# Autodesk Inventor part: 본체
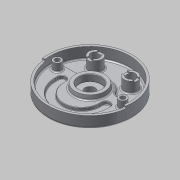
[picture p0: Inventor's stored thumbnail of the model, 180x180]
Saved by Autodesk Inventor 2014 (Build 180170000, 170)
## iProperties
Created: 2015-06
Part Number: 본체
Material: 알루미늄 6061
Document SubType Name: Modeling
Designer: MYHOME
Mass: 1071 g
Surface Area: 1034.49 cm^2
Volume: 395.202 cm^3
Density: 2.71 g/cm^3
Appearance: 알루미늄 - 평지
Author: MYHOME
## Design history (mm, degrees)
sketch "스케치1"
  geometry: C1 r 95 at (0, 0); 1 further point
  constraints: 1 centre point, 1 coincident
  dimensions: "d0" = 190 diameter of C1
extrude "돌출1" new body sketch "스케치1" distance "d1" = 32; taper "d2" = 0 deg
sketch "스케치2"
  geometry: C1 r 95 at (0, 0) reference; C2 r 90 at (0, 0)
  constraints: 1 centre point, 1 coincident
  dimensions: "d3" = 180 diameter of C2
extrude "돌출2" cut sketch "스케치2" distance "d4" = 18; taper "d5" = 0 deg
sketch "스케치3"
  geometry: L1 (-88.566, 16)-(-38.833, 16); L2 (-38.833, 16)-(38.833, 16); L3 (38.833, 16)-(88.566, 16); A1 r 90 centre (0, 0) between (88.566, 16) and (-88.566, 16) reference; A2 r 42 centre (0, 0) between (-38.833, 16) and (38.833, 16)
  constraints: 6 end point, 4 point on circle, 3 horizontal, 1 centre point, 1 coincident
  dimensions: "d6" = 84 diameter of A2; "d7" = 16 distance from line of A2.centre L1
extrude "돌출3" cut sketch "스케치3" distance "d8" = 7; taper "d9" = 0 deg
fillet "모깎기1" dims "d10" = 10
sketch "스케치4"
  geometry: L1 (75.657, 16)-(45.033, 16) reference; L2 (-50, -19)-(-50, -14); L3 (-59, -19)-(-59, -14); L4 (-41, -14)-(-41, -19); L5 (50, -19)-(50, -14); L6 (41, -19)-(41, -14); L7 (59, -14)-(59, -19); A1 r 90 centre (0, 0) between (-85.114, 29.25) and (85.114, 29.25) reference; A2 r 50 centre (0, -19) between (-50, -19) and (50, -19); A3 r 59 centre (0, -19) between (-59, -19) and (59, -19); A4 r 41 centre (0, -19) between (-41, -19) and (41, -19); A5 r 9 centre (-50, -19) between (-41, -19) and (-59, -19); A6 r 9 centre (50, -19) between (59, -19) and (41, -19); A7 r 9 centre (-50, -19) between (-59, -19) and (-41, -19); A8 r 9 centre (-50, -14) between (-41, -14) and (-59, -14); A9 r 9 centre (50, -19) between (41, -19) and (59, -19); A10 r 9 centre (50, -14) between (59, -14) and (41, -14); 2 further points
  constraints: 18 point on circle, 16 end point, 14 tangent, 9 centre point, 3 parallel, 2 horizontal alignment, 2 midpoint, 1 perpendicular, 1 vertical alignment
  dimensions: "d11" = 59 radius of A3; "d12" = 18 distance of A3.end A4.end; "d13" = 19 distance of A1.centre A2.centre; "d19" = 5 distance of L2.end L2.start; "d20" = 18 distance of L3.end L4.start; "d21" = 5 distance of L5.start L5.end; "d22" = 18 distance of L7.end L6.start
extrude "돌출4" cut sketch "스케치4" distance "d23" = 7; taper "d24" = 0 deg
sketch "스케치5"
  geometry: C1 r 15 at (-40, 52); C2 r 15 at (40, 52); A1 r 90 centre (0, 0) between (85.114, 29.25) and (-85.114, 29.25) reference
  constraints: 2 centre point, 1 horizontal alignment
  dimensions: "d25" = 30 diameter of C1; "d26" = 30 diameter of C2; "d27" = 52 vertical distance of C1.centre A1.centre; "d28" = 40 horizontal distance of A1.centre C1.centre; "d29" = 40 horizontal distance of C2.centre A1.centre
extrude "돌출5" join sketch "스케치5" stored distance "d30" = 7; taper "d31" = 0 deg
sketch "스케치6"
  geometry: C1 r 15 at (0, 0) reference; C2 r 15 at (80, 0) reference; C3 r 10 at (0, 0); C4 r 10 at (80, 0); 1 further point
  constraints: 2 centre point, 2 coincident
  dimensions: "d32" = 20 diameter of C3; "d33" = 20 diameter of C4
extrude "돌출6" cut sketch "스케치6" stored distance "d34" = 7; taper "d35" = 0 deg
sketch "스케치7"
  geometry: L1 (65, 6)-(95, 6); L2 (95, 6)-(95, -6); L3 (95, -6)-(65, -6); L4 (65, -6)-(65, 6); L5 (6, -15)-(-6, -15); L6 (-6, -15)-(-6, 15); L7 (-6, 15)-(6, 15); L8 (6, 15)-(6, -15); C1 r 10 at (0, 0) reference; C2 r 15 at (0, 0) reference; C3 r 10 at (80, 0) reference; C4 r 15 at (80, 0) reference; 3 further points
  constraints: 16 end point, 4 parallel, 4 tangent, 2 horizontal, 2 midpoint, 2 perpendicular, 1 horizontal alignment, 1 vertical alignment
  dimensions: "d36" = 12 distance of L6.end L7.end; "d37" = 12 distance of L3.end L1.start
extrude "돌출7" cut sketch "스케치7" distance "d38" = 3; taper "d39" = 0 deg
sketch "스케치8"
  geometry: C1 r 9 at (-74, 0); C2 r 9 at (74, 0); A1 r 90 centre (0, 0) between (-85.114, 29.25) and (85.114, 29.25) reference
  constraints: 2 centre point, 2 horizontal alignment
  dimensions: "d40" = 18 diameter of C1; "d41" = 18 diameter of C2; "d42" = 74 distance of A1.centre C1.centre; "d43" = 74 distance of C2.centre A1.centre
extrude "돌출8" join sketch "스케치8" stored distance "d44" = 3; taper "d45" = 0 deg
sketch "스케치9"
  geometry: C1 r 9 at (0, 0) reference; C2 r 9 at (148, 0) reference; C3 r 5.5 at (0, 0); C4 r 5.5 at (148, 0); 1 further point
  constraints: 2 centre point, 2 coincident
  dimensions: "d46" = 11 diameter of C3; "d47" = 11 diameter of C4
extrude "돌출9" cut sketch "스케치9" stored distance "d48" = 3; taper "d49" = 0 deg
sketch "스케치10"
  geometry: C1 r 5.5 at (74, 0) reference; C2 r 5.5 at (-74, 0) reference; C3 r 9 at (-74, 0); C4 r 9 at (74, 0)
  constraints: 2 centre point, 2 coincident
  dimensions: "d50" = 18 diameter of C3; "d51" = 18 diameter of C4
extrude "돌출10" cut sketch "스케치10" distance "d52" = 11; taper "d53" = 0 deg
sketch "스케치11"
  geometry: C1 r 35 at (0, 0); A1 r 42 centre (0, 0) between (36.373, 21) and (-36.373, 21) reference
  constraints: 1 centre point, 1 coincident
  dimensions: "d54" = 70 diameter of C1
extrude "돌출11" join sketch "스케치11" distance "d55" = 10; taper "d56" = -10 deg
sketch "스케치12"
  geometry: C1 r 33.237 at (0, 0) reference; C2 r 25 at (0, 0)
  constraints: 1 centre point, 1 coincident
  dimensions: "d57" = 50 diameter of C2
extrude "돌출12" cut sketch "스케치12" distance "d58" = 15; taper "d59" = 0 deg
sketch "스케치14"
  geometry: L1 (0, 0)-(89.124, -12.526); L2 (0, 0)-(-89.124, -12.526); L3 (0, 0)-(90, 0); L4 (0, 0)-(-90, 0); L5 (89.124, -12.526)-(94.075, -13.221); L6 (-89.124, -12.526)-(-94.075, -13.221); L7 (90, 0)-(95, 0); L8 (-90, 0)-(-95, 0); A1 r 90 centre (0, 0) between (89.124, -12.526) and (-89.124, -12.526) reference; A2 r 95 centre (0, 0) between (94.075, -13.221) and (-94.075, -13.221) reference
  constraints: 16 end point, 8 point on circle, 6 collinear, 2 horizontal
  dimensions: "d63" = 8 deg angle of L1 L3; "d64" = 8 deg angle of L4 L2
extrude "돌출14" cut sketch "스케치14" distance "d65" = 5; taper "d66" = 0 deg
fillet "모깎기2" dims "d67" = 0.3
chamfer "모따기1" distance "d68" = 1; stored, may be unused: second distance "d69" = 2, angle "d70" = 45 deg
sketch "스케치15"
  geometry: C1 r 11.5 at (0, 0) reference; C2 r 95 at (0, 0) reference; A1 r 68 centre (0, 0) between (-68, 0) and (68, 0); 1 further point
  constraints: 3 point on circle, 2 horizontal alignment, 1 centre point, 1 coincident, 1 vertical alignment, 1 other
  dimensions: "d71" = 68 radius of A1
feature "엠보싱1" sketch "스케치15" dims "d1" = 32, "d72" = 0.5, "d73" = 0
fillet "모깎기3" dims "d74" = 1
fillet "모깎기4" dims "d75" = 3
fillet "모깎기5" dims "d76" = 3
fillet "모깎기6" dims "d77" = 5
fillet "모깎기7" dims "d81" = 3
sketch "스케치17"
  geometry: C1 r 90 at (0, 0) reference; C2 r 26 at (0, 0)
  constraints: 1 centre point, 1 coincident
  dimensions: "d82" = 52 diameter of C2
extrude "돌출16" join sketch "스케치17" distance "d83" = 12; taper "d84" = -15 deg
sketch "스케치18"
  geometry: C1 r 22.785 at (0, 0) reference; C2 r 11.5 at (0, 0)
  constraints: 1 centre point, 1 coincident
  dimensions: "d85" = 23 diameter of C2
extrude "돌출17" cut sketch "스케치18" stored distance "d86" = 12; taper "d87" = 0 deg
chamfer "모따기2" distance "d88" = 1; stored, may be unused: second distance "d89" = 2, angle "d90" = 45 deg
fillet "모깎기8" dims "d91" = 3
node "솔리드1"
node "투영된 루프1"
node "투영된 루프2"
node "투영된 루프3"
